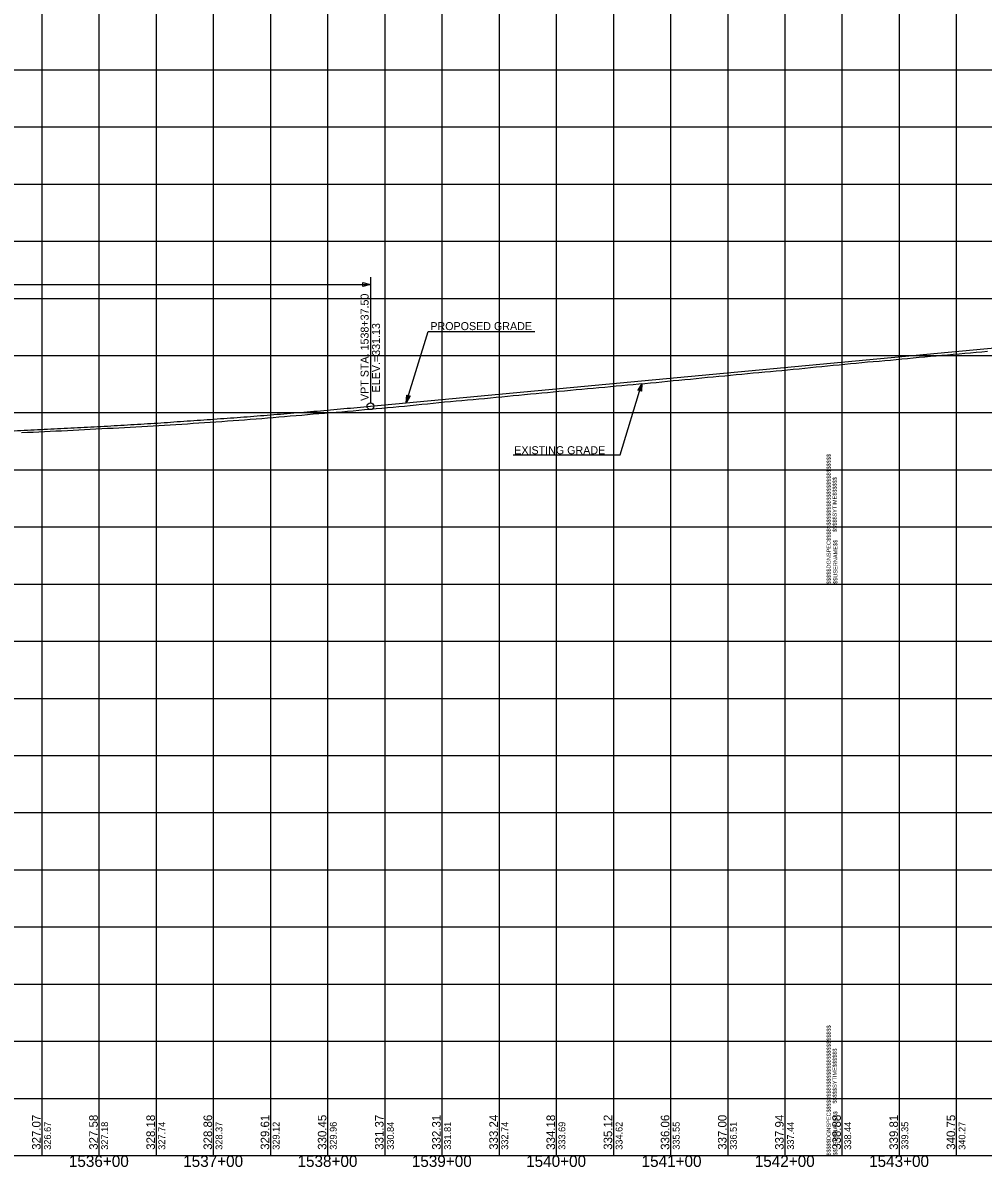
# Model space of a CAD drawing. Extents: x -90830 to 2015517, y -20856 to 836331.
# Drawn here: x 42457 to 43297, y -10807 to -9806 of the extents above; entities that cross this region are included whole.
import ezdxf

# ---------------------------------------------------------------- set-up
doc = ezdxf.new("R2010")
doc.units = 0
for name, color, linetype in [('Level 1', 7, 'Continuous'), ('RD_DDB_Profile_Elev', 7, 'Continuous'), ('RD_DDB_Profile_EX', 7, 'Continuous'), ('RD_DDB_Profile_PR', 7, 'Continuous'), ('RD_DDB_StaTX', 7, 'Continuous'), ('RD_DDB_StripGrade', 7, 'Continuous'), ('RD_DDB_VCLbl', 7, 'Continuous'), ('RD_GPK_Profile_Cell', 7, 'Continuous'), ('RD_PD_Final_TX', 7, 'Continuous')]:
    doc.layers.add(name, color=color, linetype=linetype)

msp = doc.modelspace()

# ---------------------------------------------------------------- linework, layer by layer
at = {"layer": 'Level 1'}
for p, q in [((42473.5, -9797.1), (42473.5, -10297.1)), ((42523.5, -9797.1), (42523.5, -10297.1)), ((42573.5, -9797.1), (42573.5, -10297.1)), ((42623.5, -9797.1), (42623.5, -10297.1)), ((42673.5, -9797.1), (42673.5, -10297.1)), ((42723.5, -9797.1), (42723.5, -10297.1)), ((42773.5, -9797.1), (42773.5, -10297.1)), ((42823.5, -9797.1), (42823.5, -10297.1)), ((42873.5, -9797.1), (42873.5, -10297.1)), ((42923.5, -9797.1), (42923.5, -10297.1)), ((42973.5, -9797.1), (42973.5, -10297.1)), ((43023.5, -9797.1), (43023.5, -10297.1)), ((43073.5, -9797.1), (43073.5, -10297.1)), ((43123.5, -9797.1), (43123.5, -10297.1)), ((43173.5, -9797.1), (43173.5, -10297.1)), ((43173.5, -9797.1), (43173.5, -10297.1)), ((43173.5, -9797.1), (43173.5, -10297.1)), ((43223.5, -9797.1), (43223.5, -10297.1)), ((43273.5, -9797.1), (43273.5, -10297.1)), ((41573.5, -9847.1), (43173.5, -9847.1)), ((43173.5, -9847.1), (44773.5, -9847.1)), ((41573.5, -9897.1), (43173.5, -9897.1)), ((43173.5, -9897.1), (44773.5, -9897.1)), ((41573.5, -9947.1), (43173.5, -9947.1)), ((43173.5, -9947.1), (44773.5, -9947.1)), ((41573.5, -9997.1), (43173.5, -9997.1)), ((43173.5, -9997.1), (44773.5, -9997.1)), ((41573.5, -10047.1), (43173.5, -10047.1)), ((43173.5, -10047.1), (44773.5, -10047.1)), ((41573.5, -10097.1), (43173.5, -10097.1)), ((43173.5, -10097.1), (44773.5, -10097.1)), ((41573.5, -10147.1), (43173.5, -10147.1)), ((43173.5, -10147.1), (44773.5, -10147.1)), ((41573.5, -10197.1), (43173.5, -10197.1)), ((43173.5, -10197.1), (44773.5, -10197.1)), ((41573.5, -10247.1), (43173.5, -10247.1)), ((43173.5, -10247.1), (44773.5, -10247.1)), ((41573.5, -10297.1), (43173.5, -10297.1)), ((41573.5, -10297.1), (43173.5, -10297.1)), ((42473.5, -10297.1), (42473.5, -10797.1)), ((42523.5, -10297.1), (42523.5, -10797.1)), ((42573.5, -10297.1), (42573.5, -10797.1)), ((42623.5, -10297.1), (42623.5, -10797.1)), ((42673.5, -10297.1), (42673.5, -10797.1)), ((42723.5, -10297.1), (42723.5, -10797.1)), ((42773.5, -10297.1), (42773.5, -10797.1)), ((42823.5, -10297.1), (42823.5, -10797.1)), ((42873.5, -10297.1), (42873.5, -10797.1)), ((42923.5, -10297.1), (42923.5, -10797.1)), ((42973.5, -10297.1), (42973.5, -10797.1)), ((43023.5, -10297.1), (43023.5, -10797.1)), ((43073.5, -10297.1), (43073.5, -10797.1)), ((43123.5, -10297.1), (43123.5, -10797.1)), ((43173.5, -10297.1), (43173.5, -10797.1)), ((43173.5, -10297.1), (43173.5, -10797.1)), ((43173.5, -10297.1), (44773.5, -10297.1)), ((43173.5, -10297.1), (44773.5, -10297.1)), ((43173.5, -10297.1), (43173.5, -10797.1)), ((43223.5, -10297.1), (43223.5, -10797.1)), ((43273.5, -10297.1), (43273.5, -10797.1)), ((41573.5, -10347.1), (43173.5, -10347.1)), ((43173.5, -10347.1), (44773.5, -10347.1)), ((41573.5, -10397.1), (43173.5, -10397.1)), ((43173.5, -10397.1), (44773.5, -10397.1)), ((41573.5, -10447.1), (43173.5, -10447.1)), ((43173.5, -10447.1), (44773.5, -10447.1)), ((41573.5, -10497.1), (43173.5, -10497.1)), ((43173.5, -10497.1), (44773.5, -10497.1)), ((41573.5, -10547.1), (43173.5, -10547.1)), ((43173.5, -10547.1), (44773.5, -10547.1)), ((41573.5, -10597.1), (43173.5, -10597.1)), ((43173.5, -10597.1), (44773.5, -10597.1)), ((41573.5, -10647.1), (43173.5, -10647.1)), ((43173.5, -10647.1), (44773.5, -10647.1)), ((41573.5, -10697.1), (43173.5, -10697.1)), ((43173.5, -10697.1), (44773.5, -10697.1)), ((41573.5, -10747.1), (43173.5, -10747.1)), ((43173.5, -10747.1), (44773.5, -10747.1)), ((41573.5, -10797.1), (43173.5, -10797.1)), ((43173.5, -10797.1), (44773.5, -10797.1))]:
    msp.add_line(p, q, dxfattribs=at)
at = {"layer": 'RD_DDB_Profile_EX'}
for points in [[(42920.9, -10128.9), (42925.9, -10128.4), (42930.9, -10127.9), (42935.9, -10127.5), (42940.9, -10127), (42945.9, -10126.5), (42950.9, -10126.1), (42955.9, -10125.6), (42960.9, -10125.2), (42965.9, -10124.7), (42970.9, -10124.2), (42975.9, -10123.8), (42980.9, -10123.3), (42985.9, -10122.9), (42990.9, -10122.4), (42995.9, -10121.9), (43000.9, -10121.5), (43005.9, -10121), (43010.9, -10120.6), (43015.9, -10120.1), (43020.9, -10119.6), (43025.9, -10119.1), (43030.9, -10118.7), (43035.9, -10118.2), (43040.9, -10117.7), (43045.9, -10117.2), (43050.9, -10116.7), (43055.9, -10116.2), (43060.9, -10115.7), (43065.9, -10115.3), (43070.9, -10114.8), (43075.9, -10114.3), (43080.9, -10113.8), (43085.9, -10113.4), (43090.9, -10112.9), (43095.9, -10112.4), (43100.9, -10112), (43105.9, -10111.5), (43110.9, -10111.1), (43115.9, -10110.6), (43120.9, -10110.1), (43125.9, -10109.7), (43130.9, -10109.2), (43135.9, -10108.7), (43140.9, -10108.2), (43145.9, -10107.7), (43150.9, -10107.1), (43155.9, -10106.7), (43160.9, -10106.2), (43165.9, -10105.7), (43170.9, -10105.2), (43175.9, -10104.7), (43180.9, -10104.2), (43185.9, -10103.7), (43190.9, -10103.3), (43195.9, -10102.8), (43200.9, -10102.4), (43205.9, -10102), (43210.9, -10101.6), (43215.9, -10101.1), (43220.9, -10100.6), (43225.9, -10100.1), (43230.9, -10099.6), (43235.9, -10099.1), (43240.9, -10098.7), (43245.9, -10098.2), (43250.9, -10097.8), (43255.9, -10097.3), (43260.9, -10096.9), (43265.9, -10096.4), (43270.9, -10096), (43275.9, -10095.6), (43280.9, -10095.1), (43285.9, -10094.7), (43290.9, -10094.3), (43295.9, -10093.8), (43300.9, -10093.3)], [(42455.9, -10164.5), (42460.9, -10164.3), (42465.9, -10164.1), (42470.9, -10163.9), (42475.9, -10163.7), (42480.9, -10163.4), (42485.9, -10163.1), (42490.9, -10162.9), (42495.9, -10162.6), (42500.9, -10162.4), (42505.9, -10162.1), (42510.9, -10161.9), (42515.9, -10161.6), (42520.9, -10161.4), (42525.9, -10161.1), (42530.9, -10160.8), (42535.9, -10160.6), (42540.9, -10160.3), (42545.9, -10160), (42550.9, -10159.7), (42555.9, -10159.4), (42560.9, -10159.2), (42565.9, -10158.9), (42570.9, -10158.6), (42575.9, -10158.3), (42580.9, -10158), (42585.9, -10157.7), (42590.9, -10157.4), (42595.9, -10157.1), (42600.9, -10156.8), (42605.9, -10156.4), (42610.9, -10156.1), (42615.9, -10155.8), (42620.9, -10155.4), (42625.9, -10155.1), (42630.9, -10154.8), (42635.9, -10154.4), (42640.9, -10154), (42645.9, -10153.7), (42650.9, -10153.3), (42655.9, -10152.9), (42660.9, -10152.5), (42665.9, -10152.1), (42670.9, -10151.7), (42675.9, -10151.3), (42680.9, -10150.9), (42685.9, -10150.4), (42690.9, -10150), (42695.9, -10149.6), (42700.9, -10149.2), (42705.9, -10148.7), (42710.9, -10148.3), (42715.9, -10147.9), (42720.9, -10147.5), (42725.9, -10147.1), (42730.9, -10146.7), (42735.9, -10146.3), (42740.9, -10145.9), (42745.9, -10145.4), (42750.9, -10145), (42755.9, -10144.5), (42760.9, -10144.1), (42765.9, -10143.6), (42770.9, -10143.1), (42775.9, -10142.7), (42780.9, -10142.3), (42785.9, -10141.8), (42790.9, -10141.4), (42795.9, -10140.9), (42800.9, -10140.4), (42805.9, -10139.8), (42810.9, -10139.3), (42815.9, -10138.8), (42820.9, -10138.3), (42825.9, -10137.8), (42830.9, -10137.3), (42835.9, -10136.9), (42840.9, -10136.4), (42845.9, -10135.9), (42850.9, -10135.5), (42855.9, -10135), (42860.9, -10134.6), (42865.9, -10134.1), (42870.9, -10133.6), (42875.9, -10133.2), (42880.9, -10132.7), (42885.9, -10132.2), (42890.9, -10131.8), (42895.9, -10131.3), (42900.9, -10130.8), (42905.9, -10130.4), (42910.9, -10129.9), (42915.9, -10129.4), (42920.9, -10128.9)]]:
    msp.add_lwpolyline(points, dxfattribs=at)
at = {"layer": 'RD_DDB_Profile_PR'}
msp.add_line((42761, -10141.5), (46238.5, -9815.1), dxfattribs=at)
msp.add_spline([(41596, -10141.5), (41619.3, -10143.6), (41642.6, -10145.7), (41665.9, -10147.7), (41689.2, -10149.5), (41712.5, -10151.3), (41735.8, -10153), (41759.1, -10154.7), (41782.4, -10156.2), (41805.7, -10157.6), (41829, -10159), (41852.3, -10160.2), (41875.6, -10161.4), (41898.9, -10162.5), (41922.2, -10163.5), (41945.5, -10164.4), (41968.8, -10165.3), (41992.1, -10166), (42015.4, -10166.7), (42038.7, -10167.2), (42062, -10167.7), (42085.3, -10168.1), (42108.6, -10168.4), (42131.9, -10168.6), (42155.2, -10168.8), (42178.5, -10168.8), (42201.8, -10168.8), (42225.1, -10168.6), (42248.4, -10168.4), (42271.7, -10168.1), (42295, -10167.7), (42318.3, -10167.2), (42341.6, -10166.7), (42364.9, -10166), (42388.2, -10165.3), (42411.5, -10164.4), (42434.8, -10163.5), (42458.1, -10162.5), (42481.4, -10161.4), (42504.7, -10160.2), (42528, -10159), (42551.3, -10157.6), (42574.6, -10156.2), (42597.9, -10154.6), (42621.2, -10153), (42644.5, -10151.3), (42667.8, -10149.5), (42691.1, -10147.6), (42714.4, -10145.7), (42737.7, -10143.6), (42761, -10141.5)], degree=3, dxfattribs=at)
at = {"layer": 'RD_DDB_VCLbl'}
for p, q in [((42761, -10028.6), (42761, -10138.5)), ((41596, -10035), (42761, -10035))]:
    msp.add_line(p, q, dxfattribs=at)
msp.add_circle((42761, -10141.5), 3, dxfattribs=at)
at = {"layer": 'RD_GPK_Profile_Cell'}
msp.add_line((4823.5, -10797.1), (75223.5, -10797.1), dxfattribs=at)
at = {"layer": 'RD_PD_Final_TX'}
for p, q in [((42792.3, -10138.5), (42811.4, -10076.1)), ((42811.4, -10076.1), (42904.8, -10076.1)), ((42998.4, -10121.7), (42995, -10127.4)), ((42996.6, -10127.9), (42998.4, -10121.7)), ((42998.4, -10121.7), (42998.1, -10128.4)), ((42792.3, -10138.5), (42792.7, -10131.8)), ((42792.7, -10131.8), (42795.8, -10132.8)), ((42998.1, -10128.4), (42995, -10127.4)), ((42794.2, -10132.3), (42792.3, -10138.5)), ((42792.3, -10138.5), (42795.8, -10132.8))]:
    msp.add_line(p, q, dxfattribs=at)
msp.add_lwpolyline([(42754.4, -10033.3), (42761, -10035), (42754.4, -10036.6)], close=True, dxfattribs=at)
for points in [[(42886, -10184.1), (42979.4, -10184.1), (42998.4, -10121.7)], [(42998.3, -10122.1), (42996.5, -10127.8), (42998.2, -10122.3), (42996.5, -10127.8), (42998.1, -10122.5), (42996.4, -10127.8), (42998, -10122.6), (42996.4, -10127.8), (42997.8, -10122.8), (42996.3, -10127.8), (42997.7, -10123), (42996.2, -10127.8), (42997.6, -10123.2), (42996.2, -10127.7), (42997.4, -10123.5), (42996.1, -10127.7), (42997.3, -10123.8), (42996, -10127.7), (42997.2, -10124), (42996, -10127.7), (42997, -10124.2), (42995.9, -10127.7), (42996.8, -10124.5), (42995.9, -10127.6), (42996.6, -10124.9), (42995.8, -10127.6), (42996.5, -10125.1), (42995.7, -10127.6), (42996.3, -10125.4), (42995.7, -10127.6), (42996.2, -10125.7), (42995.6, -10127.5), (42996, -10125.9), (42995.5, -10127.5), (42995.8, -10126.1), (42995.5, -10127.5), (42995.7, -10126.5), (42995.4, -10127.5), (42995.6, -10126.7), (42995.3, -10127.5), (42995.4, -10126.8), (42995.2, -10127.4), (42995.1, -10127.4), (42995.2, -10127.4)], [(42996.6, -10127.8), (42998.4, -10122.1), (42996.7, -10127.9), (42998.4, -10122.4), (42996.7, -10127.9), (42998.4, -10122.6), (42996.8, -10127.9), (42998.4, -10122.8), (42996.9, -10127.9), (42998.3, -10123.2), (42997, -10128), (42998.3, -10123.5), (42997, -10128), (42998.3, -10123.8), (42997.1, -10128), (42998.3, -10124.2), (42997.2, -10128), (42998.2, -10124.4), (42997.2, -10128.1), (42998.2, -10124.7), (42997.3, -10128.1), (42998.2, -10125.1), (42997.4, -10128.1), (42998.2, -10125.5), (42997.5, -10128.1), (42998.2, -10125.8), (42997.5, -10128.2), (42998.2, -10126.2), (42997.6, -10128.2), (42998.1, -10126.6), (42997.7, -10128.2), (42998.1, -10126.9), (42997.8, -10128.2), (42998.1, -10127.2), (42997.8, -10128.3), (42998.1, -10127.6), (42997.9, -10128.2), (42998.1, -10128), (42998, -10128.2)], [(42794.2, -10132.4), (42792.4, -10138.1), (42794.1, -10132.3), (42792.4, -10137.9), (42794.1, -10132.3), (42792.4, -10137.7), (42794, -10132.3), (42792.4, -10137.4), (42793.9, -10132.3), (42792.5, -10137.1), (42793.8, -10132.2), (42792.5, -10136.7), (42793.8, -10132.2), (42792.5, -10136.4), (42793.7, -10132.2), (42792.5, -10136.1), (42793.6, -10132.2), (42792.6, -10135.8), (42793.6, -10132.2), (42792.6, -10135.5), (42793.5, -10132.2), (42792.6, -10135.2), (42793.4, -10132.1), (42792.6, -10134.7), (42793.3, -10132.1), (42792.6, -10134.4), (42793.3, -10132.1), (42792.6, -10134), (42793.2, -10132.1), (42792.7, -10133.6), (42793.1, -10132), (42792.7, -10133.3), (42793, -10132), (42792.7, -10133), (42793, -10131.9), (42792.7, -10132.6), (42792.9, -10132), (42792.7, -10132.2), (42792.8, -10132)], [(42792.5, -10138.1), (42794.3, -10132.4), (42792.6, -10137.9), (42794.3, -10132.4), (42792.7, -10137.7), (42794.4, -10132.4), (42792.8, -10137.6), (42794.4, -10132.4), (42793, -10137.4), (42794.5, -10132.5), (42793.1, -10137.2), (42794.6, -10132.5), (42793.2, -10137), (42794.6, -10132.5), (42793.4, -10136.7), (42794.7, -10132.5), (42793.5, -10136.5), (42794.8, -10132.5), (42793.6, -10136.2), (42794.8, -10132.5), (42793.8, -10136), (42794.9, -10132.6), (42793.9, -10135.7), (42794.9, -10132.6), (42794.2, -10135.4), (42795, -10132.6), (42794.3, -10135.1), (42795.1, -10132.6), (42794.5, -10134.9), (42795.1, -10132.6), (42794.6, -10134.6), (42795.2, -10132.7), (42794.8, -10134.3), (42795.3, -10132.7), (42794.9, -10134.1), (42795.3, -10132.8), (42795.1, -10133.7), (42795.4, -10132.7), (42795.2, -10133.5), (42795.5, -10132.8), (42795.4, -10133.4), (42795.6, -10132.9), (42795.7, -10132.8), (42795.6, -10132.8)]]:
    msp.add_lwpolyline(points, dxfattribs=at)

# ---------------------------------------------------------------- texts
at = {"layer": 'Level 1'}
for s, p in [('$$$$$DGNSPEC$$$$$$$$$$$$$$$$$$$$$$$$$$$$', (43163.6, -10297.2)), ('$$$$$SYTIME$$$$$$', (43168.9, -10251.6)), ('$$USERNAME$$', (43169.5, -10297)), ('$$$$$DGNSPEC$$$$$$$$$$$$$$$$$$$$$$$$$$$$', (43163.6, -10797.2)), ('$$$$$SYTIME$$$$$$', (43168.9, -10751.6)), ('$$USERNAME$$', (43169.5, -10797))]:
    msp.add_text(s, height=3.544, rotation=90, dxfattribs=at).set_placement(p)
at = {"layer": 'RD_DDB_Profile_Elev'}
for s, p in [('327.07', (42472.5, -10792.1)), ('327.58', (42522.5, -10792.1)), ('328.18', (42572.5, -10792.1)), ('328.86', (42622.5, -10792.1)), ('329.61', (42672.5, -10792.1)), ('330.45', (42722.5, -10792.1)), ('331.37', (42772.5, -10792.1)), ('332.31', (42822.5, -10792.1)), ('333.24', (42872.5, -10792.1)), ('334.18', (42922.5, -10792.1)), ('335.12', (42972.5, -10792.1)), ('336.06', (43022.5, -10792.1)), ('337.00', (43072.5, -10792.1)), ('337.94', (43122.5, -10792.1)), ('338.88', (43172.5, -10792.1)), ('339.81', (43222.5, -10792.1)), ('340.75', (43272.5, -10792.1))]:
    msp.add_text(s, height=7.5, rotation=90, dxfattribs=at).set_placement(p)
at = {"layer": 'RD_DDB_StaTX'}
for s, p in [('1536+00', (42497.2, -10807.1)), ('1537+00', (42597.2, -10807.1)), ('1538+00', (42697.2, -10807.1)), ('1539+00', (42797.2, -10807.1)), ('1540+00', (42897.2, -10807.1)), ('1541+00', (42998.2, -10807.1)), ('1542+00', (43097.2, -10807.1)), ('1543+00', (43197.2, -10807.1))]:
    msp.add_text(s, height=10, dxfattribs=at).set_placement(p)
at = {"layer": 'RD_DDB_StripGrade'}
for s, height, p in [('VPT STA. 1538+37.50 ', 7, (42759.4, -10136.9)), ('ELEV.=331.13', 7, (42769.4, -10129.4)), ('326.67', 6, (42481.5, -10792.1)), ('327.18', 6, (42531.5, -10792.1)), ('327.74', 6, (42581.5, -10792.1)), ('328.37', 6, (42631.5, -10792.1)), ('329.12', 6, (42681.5, -10792.1)), ('329.96', 6, (42731.5, -10792.1)), ('330.84', 6, (42781.5, -10792.1)), ('331.81', 6, (42831.5, -10792.1)), ('332.74', 6, (42881.5, -10792.1)), ('333.69', 6, (42931.5, -10792.1)), ('334.62', 6, (42981.5, -10792.1)), ('335.55', 6, (43031.5, -10792.1)), ('336.51', 6, (43081.5, -10792.1)), ('337.44', 6, (43131.5, -10792.1)), ('338.44', 6, (43181.5, -10792.1)), ('339.35', 6, (43231.5, -10792.1)), ('340.27', 6, (43281.5, -10792.1))]:
    msp.add_text(s, height=height, rotation=90, dxfattribs=at).set_placement(p)
at = {"layer": 'RD_PD_Final_TX'}
for s, p in [('PROPOSED GRADE', (42813.4, -10074.9)), ('EXISTING GRADE', (42886.8, -10183.5))]:
    msp.add_text(s, height=7, dxfattribs=at).set_placement(p)

doc.saveas('drawing.dxf')
